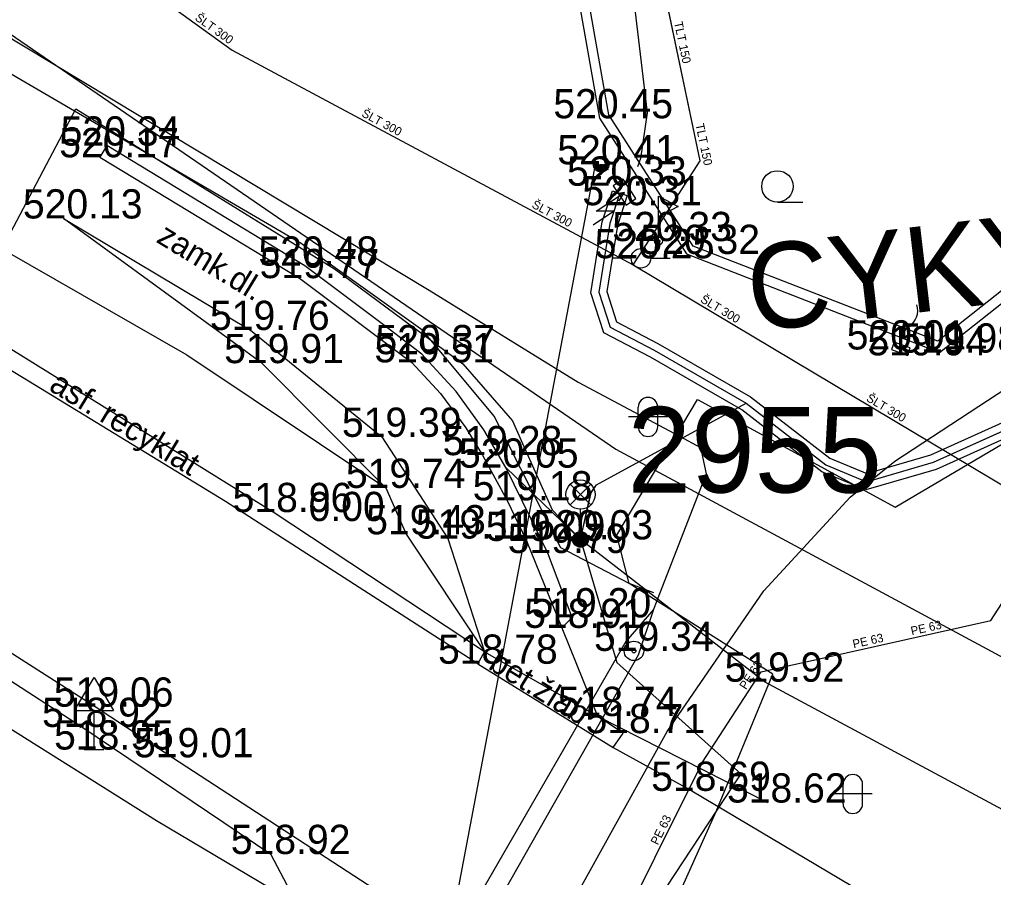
# Model space of a CAD drawing. Extents: x -668867 to -667827, y -1131943 to -1131019.
# Drawn here: x -668478.76 to -668453.79, y -1131449.79 to -1131427.79 of the extents above; entities that cross this region are included whole.
import ezdxf

# ---------------------------------------------------------------- set-up
doc = ezdxf.new("R2010")
doc.units = 0
for name, color, linetype in [('G_Bod_tecka', 7, 'Continuous'), ('G_Bod_vyska', 7, 'Continuous'), ('G_Breh_Teren', 7, 'Continuous'), ('G_Cesty_Schody', 7, 'Continuous'), ('G_Objekty_dopravni', 7, 'Continuous'), ('G_Objekty_technicke', 7, 'Continuous'), ('G_Plochy_zpevnene', 7, 'Continuous'), ('G_Ploty', 7, 'Continuous'), ('G_Popisy_povrchu', 7, 'Continuous'), ('G_Site-Rozvadece', 7, 'Continuous'), ('G_Site-Sloupy', 7, 'Continuous'), ('G_Site-vodovod', 7, 'Continuous'), ('G_Z_CHRANICKA-TEPLOVOD_kotovane', 7, 'Continuous'), ('G_Z_ELsilove_nadz_kotovane', 7, 'Continuous'), ('G_Z_ELsilove_podz_kotovane', 7, 'Continuous'), ('G_Z_PLYNY_podz_geodeticky', 7, 'Continuous'), ('G_Z_SPOJE_podz_geodeticky', 7, 'Continuous'), ('G_Z_SPOJE_podz_kotovane', 7, 'Continuous'), ('G_Z_SPOJE_podz_priblizne', 7, 'Continuous'), ('G_Z_VODA_podz_kotovane', 7, 'Continuous'), ('G_Zabradli_Svodidla', 7, 'Continuous'), ('G_Zelen-Znacky', 7, 'Continuous'), ('Vrstva 1', 7, 'Continuous'), ('Vrstva 17', 7, 'Continuous'), ('Vrstva 26', 7, 'Continuous'), ('Vrstva 3', 7, 'Continuous'), ('Vrstva 4', 7, 'Continuous'), ('Vrstva 6', 7, 'Continuous')]:
    doc.layers.add(name, color=color, linetype=linetype)

msp = doc.modelspace()

# ---------------------------------------------------------------- linework, layer by layer
at = {"layer": 'G_Bod_tecka'}
for p, q in [((-668463.89, -1131430.32), (-668463.89, -1131430.32)), ((-668476.52, -1131431.02), (-668476.52, -1131431.02)), ((-668476.7, -1131431.32), (-668476.7, -1131431.32)), ((-668463.85, -1131431.5), (-668463.85, -1131431.5)), ((-668463.54, -1131432.05), (-668463.54, -1131432.05)), ((-668463.21, -1131432.55), (-668463.21, -1131432.55)), ((-668477.63, -1131432.89), (-668477.63, -1131432.89)), ((-668462.38, -1131433.47), (-668462.38, -1131433.47)), ((-668462.83, -1131433.91), (-668462.83, -1131433.91)), ((-668461.66, -1131433.8), (-668461.66, -1131433.8)), ((-668471.45, -1131434.1), (-668471.45, -1131434.1)), ((-668471.58, -1131434.42), (-668471.58, -1131434.42)), ((-668472.84, -1131435.75), (-668472.84, -1131435.75)), ((-668468.45, -1131436.37), (-668468.45, -1131436.37)), ((-668456.41, -1131436.25), (-668456.41, -1131436.25)), ((-668456, -1131436.4), (-668456, -1131436.4)), ((-668455.18, -1131436.33), (-668455.18, -1131436.33)), ((-668472.55, -1131436.6), (-668472.55, -1131436.6)), ((-668468.7, -1131436.58), (-668468.7, -1131436.58)), ((-668469.47, -1131438.49), (-668469.47, -1131438.49)), ((-668466.89, -1131438.96), (-668466.89, -1131438.96)), ((-668466.29, -1131439.28), (-668466.29, -1131439.28)), ((-668469.37, -1131439.8), (-668469.37, -1131439.8)), ((-668466.26, -1131440.12), (-668466.26, -1131440.12)), ((-668472.26, -1131440.42), (-668472.26, -1131440.42)), ((-668470.57, -1131440.65), (-668470.57, -1131440.65)), ((-668468.85, -1131440.99), (-668468.85, -1131440.99)), ((-668467.78, -1131441.1), (-668467.78, -1131441.1)), ((-668465.76, -1131441.16), (-668465.76, -1131441.16)), ((-668464.38, -1131441.12), (-668464.38, -1131441.12)), ((-668465.22, -1131441.47), (-668465.22, -1131441.47)), ((-668464.59, -1131443.12), (-668464.59, -1131443.12)), ((-668464.86, -1131443.39), (-668464.86, -1131443.39)), ((-668463.01, -1131443.98), (-668463.01, -1131443.98)), ((-668467.01, -1131444.31), (-668467.01, -1131444.31)), ((-668459.66, -1131444.77), (-668459.66, -1131444.77)), ((-668476.82, -1131445.41), (-668476.82, -1131445.41)), ((-668463.94, -1131445.65), (-668463.94, -1131445.65)), ((-668477.16, -1131445.93), (-668477.16, -1131445.93)), ((-668463.29, -1131446.09), (-668463.29, -1131446.09)), ((-668476.85, -1131446.51), (-668476.85, -1131446.51)), ((-668474.84, -1131446.71), (-668474.84, -1131446.71)), ((-668461.53, -1131447.57), (-668461.53, -1131447.57)), ((-668459.59, -1131447.87), (-668459.59, -1131447.87)), ((-668472.32, -1131449.19), (-668472.32, -1131449.19))]:
    msp.add_line(p, q, dxfattribs=at)
at = {"layer": 'G_Breh_Teren'}
for p, q in [((-668464.38, -1131441.12), (-668466.29, -1131439.28)), ((-668459.66, -1131444.77), (-668464.38, -1131441.12)), ((-668463.94, -1131445.65), (-668459.59, -1131447.87))]:
    msp.add_line(p, q, dxfattribs=at)
for points in [[(-668469.37, -1131439.8), (-668472.55, -1131436.6), (-668477.63, -1131432.89)], [(-668479.2, -1131433.68), (-668474.47, -1131436.39), (-668469.37, -1131439.8), (-668468.85, -1131440.99), (-668466.84, -1131444)], [(-668466.84, -1131444), (-668472.26, -1131440.42), (-668481, -1131434.99)], [(-668410.2, -1131469.94), (-668412.45, -1131469.01), (-668422.03, -1131465.1), (-668426.97, -1131463.16), (-668431.89, -1131461.2), (-668435.72, -1131459.4), (-668438.96, -1131457.61), (-668444.44, -1131454.13), (-668452.52, -1131448.61), (-668459.66, -1131444.77)], [(-668464.92, -1131460.24), (-668470.3, -1131453.02), (-668472.32, -1131449.19)]]:
    msp.add_lwpolyline(points, dxfattribs=at)
at = {"layer": 'G_Cesty_Schody'}
msp.add_line((-668466.84, -1131444), (-668463.94, -1131445.65), dxfattribs=at)
at = {"layer": 'G_Objekty_dopravni'}
for p, q in [((-668477.35, -1131445.51), (-668476.85, -1131444.66)), ((-668476.85, -1131444.66), (-668476.35, -1131445.51)), ((-668477.35, -1131445.51), (-668476.35, -1131445.51)), ((-668476.85, -1131446.51), (-668476.85, -1131445.51)), ((-668477.1, -1131446.51), (-668476.6, -1131446.51))]:
    msp.add_line(p, q, dxfattribs=at)
at = {"layer": 'G_Objekty_technicke'}
for p, q in [((-668464.645, -1131439.705), (-668464.115, -1131440.235)), ((-668464.645, -1131440.235), (-668464.115, -1131439.705)), ((-668464.38, -1131441.12), (-668464.38, -1131440.345))]:
    msp.add_line(p, q, dxfattribs=at)
for centre, radius in [((-668464.38, -1131439.97), 0.375), ((-668464.38, -1131441.12), 0.2), ((-668464.38, -1131441.12), 0.18), ((-668464.38, -1131441.12), 0.16), ((-668464.38, -1131441.12), 0.14), ((-668464.38, -1131441.12), 0.12), ((-668464.38, -1131441.12), 0.1), ((-668464.38, -1131441.12), 0.08), ((-668464.38, -1131441.12), 0.06), ((-668464.38, -1131441.12), 0.04), ((-668464.38, -1131441.12), 0.02)]:
    msp.add_circle(centre, radius, dxfattribs=at)
at = {"layer": 'G_Plochy_zpevnene'}
for p, q in [((-668476.52, -1131431.02), (-668476.7, -1131431.32)), ((-668464.86, -1131443.39), (-668464.59, -1131443.12)), ((-668464.86, -1131443.39), (-668463.94, -1131445.65)), ((-668467.01, -1131444.31), (-668466.84, -1131444)), ((-668467.01, -1131444.31), (-668463.54, -1131446.46)), ((-668463.54, -1131446.46), (-668461.53, -1131447.57))]:
    msp.add_line(p, q, dxfattribs=at)
for points in [[(-668467.01, -1131444.31), (-668473.48, -1131440.15), (-668479.5, -1131436.47), (-668488.51, -1131430.88), (-668492.82, -1131428.04), (-668497.12, -1131424.95), (-668504.86, -1131419.02), (-668510.28, -1131414.86)], [(-668464.59, -1131443.12), (-668465.22, -1131441.47), (-668466.29, -1131439.28), (-668466.86, -1131438.31), (-668467.57, -1131437.33), (-668467.98, -1131436.88), (-668468.45, -1131436.37), (-668469.43, -1131435.62), (-668471.45, -1131434.1), (-668476.52, -1131431.02)], [(-668476.7, -1131431.32), (-668471.58, -1131434.42), (-668468.7, -1131436.58), (-668467.97, -1131437.38), (-668467.32, -1131438.26), (-668466.89, -1131438.96), (-668466.26, -1131440.12), (-668465.76, -1131441.16), (-668464.86, -1131443.39)], [(-668477.63, -1131432.89), (-668472.84, -1131435.75), (-668469.47, -1131438.49)], [(-668469.47, -1131438.49), (-668467.78, -1131441.1), (-668466.84, -1131444)], [(-668484.51, -1131440.49), (-668476.82, -1131445.41), (-668474.84, -1131446.71)], [(-668463.54, -1131446.46), (-668463.29, -1131446.09), (-668463.94, -1131445.65)], [(-668474.84, -1131446.71), (-668468.94, -1131450.55), (-668467.41, -1131451.55)], [(-668461.53, -1131447.57), (-668448.14, -1131455.53)]]:
    msp.add_lwpolyline(points, dxfattribs=at)
at = {"layer": 'G_Ploty'}
for p, q in [((-668422.71, -1131410.22), (-668455.22, -1131436.04)), ((-668455.18, -1131436.33), (-668422.58, -1131410.44)), ((-668465.97, -1131418.51), (-668463.89, -1131430.32)), ((-668463.65, -1131430.23), (-668465.7, -1131418.63)), ((-668463.89, -1131430.32), (-668461.66, -1131433.8)), ((-668461.49, -1131433.6), (-668463.65, -1131430.23)), ((-668455.22, -1131436.04), (-668461.49, -1131433.6)), ((-668461.66, -1131433.8), (-668455.18, -1131436.33))]:
    msp.add_line(p, q, dxfattribs=at)
at = {"layer": 'G_Site-Rozvadece'}
for p, q in [((-668463.98, -1131432.702), (-668463.25, -1131432.22)), ((-668463.25, -1131432.22), (-668463.515, -1131432.263)), ((-668463.394, -1131432.447), (-668463.25, -1131432.22)), ((-668464.052, -1131433.049), (-668463.53, -1131432.704)), ((-668463.53, -1131432.704), (-668463.98, -1131432.702))]:
    msp.add_line(p, q, dxfattribs=at)
for points in [[(-668463.29, -1131431.88), (-668463.54, -1131432.05), (-668463.21, -1131432.55), (-668462.96, -1131432.38)], [(-668456.34, -1131436.06), (-668456.41, -1131436.25), (-668456, -1131436.4), (-668455.93, -1131436.21)]]:
    msp.add_lwpolyline(points, close=True, dxfattribs=at)
for centre, start, end in [((-668456.236, -1131435.248), 303.0349, 16.7747), ((-668455.691, -1131436.086), 123.0349, 196.7747)]:
    msp.add_arc(centre, 0.5, start, end, dxfattribs=at)
at = {"layer": 'G_Site-Sloupy'}
for centre, radius in [((-668463.85, -1131431.5), 0.2), ((-668463.01, -1131443.98), 0.25), ((-668463.01, -1131443.98), 0.05)]:
    msp.add_circle(centre, radius, dxfattribs=at)
for radius in [0.18, 0.16, 0.14, 0.12, 0.1, 0.08, 0.06, 0.04, 0.02]:
    msp.add_arc((-668463.85, -1131431.5), radius, 180, 0, dxfattribs=at)
at = {"layer": 'G_Site-vodovod'}
for p, q in [((-668462.38, -1131433.47), (-668462.38, -1131432.32)), ((-668462.38, -1131432.32), (-668461.88, -1131432.585)), ((-668461.88, -1131432.585), (-668462.38, -1131432.85)), ((-668463.08, -1131433.91), (-668463.58, -1131433.91)), ((-668462.58, -1131433.91), (-668462.08, -1131433.91))]:
    msp.add_line(p, q, dxfattribs=at)
for centre, radius in [((-668462.38, -1131433.47), 0.1), ((-668462.38, -1131433.47), 0.0348), ((-668462.83, -1131433.91), 0.25)]:
    msp.add_circle(centre, radius, dxfattribs=at)
at = {"layer": 'G_Z_CHRANICKA-TEPLOVOD_kotovane'}
msp.add_lwpolyline([(-668451.154, -1131437.475), (-668455.261, -1131439.328), (-668457.062, -1131439.852), (-668458.191, -1131439.385), (-668460.242, -1131437.797), (-668462.586, -1131436.445), (-668463.785, -1131435.819), (-668464.115, -1131434.796), (-668463.825, -1131432.972), (-668463.56, -1131432.177), (-668463.18, -1131432.303), (-668463.435, -1131433.068), (-668463.705, -1131434.764), (-668463.455, -1131435.541), (-668462.394, -1131436.095), (-668460.018, -1131437.464), (-668457.989, -1131439.035), (-668457.038, -1131439.428), (-668455.399, -1131438.952), (-668451.306, -1131437.105)], dxfattribs=at)
at = {"layer": 'G_Z_ELsilove_nadz_kotovane'}
msp.add_lwpolyline([(-668464.007, -1131431.501), (-668468.689, -1131456.254)], dxfattribs=at)
at = {"layer": 'G_Z_ELsilove_podz_kotovane'}
for points in [[(-668462.466, -1131415.878), (-668463.066, -1131416.102), (-668465.12, -1131417.371), (-668464.957, -1131417.667), (-668464.671, -1131418.127), (-668463.236, -1131425.448), (-668462.671, -1131430.184), (-668462.843, -1131431.348), (-668462.921, -1131431.567)], [(-668479.08, -1131433.42), (-668477.32, -1131430.08), (-668470.69, -1131434.18), (-668467.4, -1131436.62), (-668466.12, -1131438.08), (-668465.9, -1131438.58), (-668465.11, -1131440.36), (-668464.38, -1131441.12), (-668464.11, -1131439.93), (-668463.97, -1131439.72), (-668460.13, -1131437.63), (-668458.09, -1131439.21), (-668457.05, -1131439.64), (-668455.33, -1131439.14), (-668451.23, -1131437.29), (-668445.76, -1131435.29), (-668442.87, -1131434.29), (-668441.69, -1131434.19), (-668441, -1131434.65), (-668440.33, -1131435.54)], [(-668464.007, -1131431.501), (-668463.674, -1131431.631)], [(-668463.37, -1131432.24), (-668463.63, -1131433.02), (-668463.91, -1131434.78), (-668463.62, -1131435.68), (-668462.49, -1131436.27), (-668460.13, -1131437.63), (-668458.09, -1131439.21), (-668457.05, -1131439.64), (-668455.33, -1131439.14), (-668451.23, -1131437.29), (-668445.76, -1131435.29), (-668444.08, -1131434.71), (-668442.87, -1131434.29), (-668441.69, -1131434.19), (-668441, -1131434.65)]]:
    msp.add_lwpolyline(points, dxfattribs=at)
at = {"layer": 'G_Z_PLYNY_podz_geodeticky'}
for points in [[(-668527.07, -1131410.75), (-668526.96, -1131410.87), (-668518.02, -1131418.51), (-668504.27, -1131428.9), (-668488.88, -1131439.82), (-668483.02, -1131443.45), (-668475.25, -1131448.33), (-668467.04, -1131453.21), (-668466.91, -1131453.3)], [(-668466.91, -1131453.3), (-668466.34, -1131453.63), (-668466.19, -1131453.33), (-668462.16, -1131446.05), (-668459.68, -1131442.44), (-668457.47, -1131440.04), (-668456.32, -1131439.11), (-668452.51, -1131436.62), (-668449.67, -1131435.17), (-668443.14, -1131432.27), (-668440.01, -1131430.74), (-668439.87, -1131430.65), (-668438.84, -1131430.02), (-668437.4, -1131432.29), (-668432.91, -1131437.47), (-668430.75, -1131440.01), (-668430.54, -1131440.3), (-668423.58, -1131448.32), (-668421.78, -1131450.38), (-668421.22, -1131451.02), (-668410.5, -1131463.68), (-668402.92, -1131461.91)]]:
    msp.add_lwpolyline(points, dxfattribs=at)
at = {"layer": 'G_Z_SPOJE_podz_geodeticky'}
for points in [[(-668583.62, -1131321.19), (-668582.19, -1131323.51), (-668579.37, -1131327.17), (-668571.26, -1131336.86), (-668560.31, -1131349.9), (-668548.78, -1131363.59), (-668541.66, -1131371.99), (-668528.88, -1131387.3), (-668520.15, -1131397.77), (-668514.25, -1131404.37), (-668511.63, -1131405.99), (-668507.04, -1131408.92), (-668502.16, -1131412.29), (-668495.34, -1131417.18), (-668487.38, -1131422.8), (-668480.13, -1131427.58), (-668468.26, -1131434.73), (-668464.44, -1131437.09), (-668461.84, -1131438.47)], [(-668504.73, -1131410.5), (-668463.47, -1131438.81), (-668419.51, -1131462.48), (-668373.54, -1131482.21), (-668331.41, -1131509.31)], [(-668461.84, -1131438.47), (-668461.3, -1131438.76)], [(-668461.3, -1131438.76), (-668461.16, -1131439.44), (-668462.46, -1131442.78)], [(-668462.51, -1131442.92), (-668463.22, -1131443.74), (-668467.94, -1131451.93), (-668467.94, -1131452.6), (-668467.69, -1131453.33)], [(-668462.51, -1131442.92), (-668462.9, -1131444.09), (-668467.46, -1131452.12), (-668467.64, -1131452.72), (-668467.69, -1131453.33)], [(-668462.46, -1131442.78), (-668462.51, -1131442.92)]]:
    msp.add_lwpolyline(points, dxfattribs=at)
at = {"layer": 'G_Z_SPOJE_podz_kotovane'}
for points in [[(-668463.13, -1131442.25), (-668464.88, -1131441.34), (-668466.59, -1131437.96), (-668468.42, -1131435.76), (-668471.54, -1131433.53), (-668482.25, -1131427.27), (-668487.56, -1131424.24), (-668492.8, -1131420.67), (-668510.89, -1131407.04), (-668515.03, -1131403.42), (-668521.28, -1131395.98)], [(-668463.13, -1131442.25), (-668463.45, -1131441.01), (-668461.38, -1131437.53), (-668456.31, -1131440.29), (-668445.54, -1131433.93), (-668442.84, -1131433.81), (-668440.64, -1131435.22)], [(-668464.48, -1131457.55), (-668463.72, -1131454.38), (-668460.9, -1131448.1), (-668459.45, -1131444.58), (-668463.13, -1131442.25)], [(-668462.5, -1131442.49), (-668463.13, -1131442.25)]]:
    msp.add_lwpolyline(points, dxfattribs=at)
at = {"layer": 'G_Z_SPOJE_podz_priblizne'}
msp.add_lwpolyline([(-668504.73, -1131410.5), (-668463.47, -1131438.81), (-668419.51, -1131462.48), (-668373.54, -1131482.21), (-668331.41, -1131509.31)], dxfattribs=at)
at = {"layer": 'G_Z_VODA_podz_kotovane'}
for points in [[(-668683.369, -1131181.224), (-668649.8, -1131211.72), (-668646.34, -1131215.79), (-668601.09, -1131269.33), (-668550.43, -1131331.42), (-668550.07, -1131333.92), (-668545.5, -1131360.28), (-668544.8, -1131361.58), (-668534.06, -1131374.68), (-668512.85, -1131400.04), (-668473.31, -1131428.57), (-668463.03, -1131434.08), (-668452.78, -1131440.2), (-668452.76, -1131440.21)], [(-668463.03, -1131434.08), (-668462.87, -1131433.83), (-668461.31, -1131431.41), (-668465.17, -1131413.01)], [(-668434.73, -1131472.73), (-668436.68, -1131471.68), (-668438.61, -1131470.64), (-668443.89, -1131467.82), (-668450.26, -1131464.4), (-668451.23, -1131463.88), (-668455.97, -1131461.29), (-668459.35, -1131459.44), (-668460.93, -1131458.58), (-668462.93, -1131456.81), (-668464.59, -1131455.47), (-668464.93, -1131454.21), (-668461.25, -1131446.83), (-668459.75, -1131444.52), (-668453.86, -1131443.2), (-668452.53, -1131441.14), (-668452.41, -1131441.01)]]:
    msp.add_lwpolyline(points, dxfattribs=at)
at = {"layer": 'G_Zabradli_Svodidla'}
for p, q in [((-668484.9, -1131440.92), (-668477.16, -1131445.93)), ((-668477.16, -1131445.93), (-668472.32, -1131449.19))]:
    msp.add_line(p, q, dxfattribs=at)
at = {"layer": 'G_Zelen-Znacky'}
for p, q in [((-668459.332, -1131432.47), (-668458.682, -1131432.467)), ((-668462.9, -1131438.23), (-668462.9, -1131437.73)), ((-668462.4, -1131438.23), (-668462.4, -1131437.73)), ((-668462.15, -1131437.98), (-668463.15, -1131437.98)), ((-668457.65, -1131447.9), (-668457.65, -1131447.4)), ((-668457.15, -1131447.9), (-668457.15, -1131447.4)), ((-668456.9, -1131447.65), (-668457.9, -1131447.65))]:
    msp.add_line(p, q, dxfattribs=at)
msp.add_circle((-668459.332, -1131432.067), 0.403, dxfattribs=at)
for centre, start, end in [((-668462.65, -1131437.73), 0, 180), ((-668462.65, -1131438.23), 180, 0), ((-668457.4, -1131447.4), 0, 180), ((-668457.4, -1131447.9), 180, 0)]:
    msp.add_arc(centre, 0.25, start, end, dxfattribs=at)
at = {"layer": 'Vrstva 1'}
for p, q in [((-668455.33, -1131439.14), (-668451.23, -1131437.29)), ((-668463.97, -1131439.72), (-668460.13, -1131437.63)), ((-668460.13, -1131437.63), (-668458.09, -1131439.21)), ((-668457.05, -1131439.64), (-668455.33, -1131439.14)), ((-668458.09, -1131439.21), (-668457.05, -1131439.64)), ((-668464.38, -1131441.12), (-668464.112, -1131439.926)), ((-668464.112, -1131439.926), (-668463.97, -1131439.72)), ((-668464.38, -1131441.12), (-668464.38, -1131441.12)), ((-668464.38, -1131441.12), (-668463.451, -1131444.28)), ((-668463.451, -1131444.28), (-668460.27, -1131447.137)), ((-668460.27, -1131447.137), (-668460.456, -1131447.419)), ((-668460.456, -1131447.419), (-668464.93, -1131454.21))]:
    msp.add_line(p, q, dxfattribs=at)
at = {"layer": 'Vrstva 17'}
for p, q in [((-668479.08, -1131433.42), (-668477.32, -1131430.08)), ((-668477.32, -1131430.08), (-668470.69, -1131434.18)), ((-668470.69, -1131434.18), (-668467.4, -1131436.62)), ((-668467.4, -1131436.62), (-668466.12, -1131438.08)), ((-668466.12, -1131438.08), (-668465.9, -1131438.58)), ((-668465.9, -1131438.58), (-668465.11, -1131440.36)), ((-668465.11, -1131440.36), (-668464.38, -1131441.12))]:
    msp.add_line(p, q, dxfattribs=at)
at = {"layer": 'Vrstva 26'}
for points in [[(-668683.369, -1131181.224), (-668649.798, -1131211.717), (-668646.336, -1131215.786), (-668601.09, -1131269.326), (-668550.43, -1131331.42), (-668550.07, -1131333.92), (-668545.496, -1131360.279), (-668544.8, -1131361.58), (-668534.06, -1131374.68), (-668512.85, -1131400.04), (-668473.31, -1131428.57), (-668463.033, -1131434.082), (-668452.779, -1131440.199), (-668452.76, -1131440.21)], [(-668463.033, -1131434.082), (-668462.87, -1131433.83), (-668461.31, -1131431.41), (-668465.171, -1131413.013)], [(-668434.733, -1131472.726), (-668436.677, -1131471.683), (-668438.615, -1131470.642), (-668443.886, -1131467.815), (-668450.263, -1131464.398), (-668451.23, -1131463.88), (-668455.966, -1131461.292), (-668459.354, -1131459.441), (-668460.93, -1131458.58), (-668462.929, -1131456.807), (-668464.59, -1131455.47), (-668464.93, -1131454.21), (-668461.25, -1131446.83), (-668459.75, -1131444.52), (-668453.86, -1131443.2), (-668452.53, -1131441.14), (-668452.41, -1131441.01)]]:
    msp.add_lwpolyline(points, dxfattribs=at)
at = {"layer": 'Vrstva 6'}
msp.add_line((-668462.87, -1131433.83), (-668462.87, -1131433.83), dxfattribs=at)

# ---------------------------------------------------------------- texts
at = {"layer": 'G_Bod_vyska'}
for s, p in [('520.45', (-668465.076, -1131430.32)), ('520.34', (-668477.706, -1131431.02)), ('520.17', (-668477.744, -1131431.32)), ('520.41', (-668464.974, -1131431.5)), ('520.33', (-668464.726, -1131432.05)), ('520.31', (-668464.334, -1131432.55)), ('520.13', (-668478.674, -1131432.89)), ('520.33', (-668463.566, -1131433.47)), ('520.25', (-668464.016, -1131433.91)), ('520.32', (-668462.846, -1131433.8)), ('520.48', (-668472.636, -1131434.1)), ('519.77', (-668472.604, -1131434.42)), ('519.76', (-668473.878, -1131435.75)), ('520.37', (-668469.636, -1131436.37)), ('520.01', (-668457.556, -1131436.25)), ('519.94', (-668457.026, -1131436.4)), ('519.98', (-668456.206, -1131436.33)), ('519.91', (-668473.514, -1131436.6)), ('519.51', (-668469.663, -1131436.58)), ('519.39', (-668470.496, -1131438.49)), ('519.28', (-668467.914, -1131438.96)), ('520.05', (-668467.497, -1131439.28)), ('519.74', (-668470.394, -1131439.8)), ('519.18', (-668467.143, -1131440.12)), ('518.96', (-668473.298, -1131440.42)), ('0.00', (-668471.35, -1131440.65)), ('519.43', (-668469.874, -1131440.99)), ('519.11', (-668468.601, -1131441.1)), ('519.09', (-668466.808, -1131441.16)), ('520.03', (-668465.587, -1131441.12)), ('519.79', (-668466.246, -1131441.47)), ('519.20', (-668465.636, -1131443.12)), ('518.91', (-668465.823, -1131443.39)), ('519.34', (-668464.034, -1131443.98)), ('518.78', (-668468.032, -1131444.31)), ('519.92', (-668460.686, -1131444.77)), ('519.06', (-668477.88, -1131445.41)), ('518.74', (-668464.962, -1131445.65)), ('518.92', (-668478.184, -1131445.93)), ('518.71', (-668464.251, -1131446.09)), ('518.95', (-668477.874, -1131446.51)), ('519.01', (-668475.824, -1131446.71)), ('518.69', (-668462.568, -1131447.57)), ('518.62', (-668460.626, -1131447.87)), ('518.92', (-668473.344, -1131449.19))]:
    msp.add_text(s, height=0.75, dxfattribs=at).set_placement(p)
at = {"layer": 'G_Popisy_povrchu'}
for s, rotation, p in [('zamk.dl.', 328.7602, (-668475.283, -1131433.48)), ('asf. recyklat', 328.6206, (-668478.036, -1131437.277)), ('bet.žlab', 328.2178, (-668466.774, -1131444.421))]:
    msp.add_text(s, height=0.6, rotation=rotation, dxfattribs=at).set_placement(p)
at = {"layer": 'Vrstva 3'}
msp.add_text('CYKY 5Cx10', height=2.1939, rotation=6.6925, dxfattribs=at).set_placement((-668459.975, -1131435.803))
at = {"layer": 'Vrstva 4'}
for s, rotation, p in [('ŠLT 300', 324.1907, (-668474.28, -1131427.783)), ('TLT 150', 281.8403, (-668461.983, -1131427.861)), ('ŠLT 300', 331.7537, (-668470.011, -1131430.259)), ('TLT 150', 281.8711, (-668461.434, -1131430.476)), ('ŠLT 300', 331.7537, (-668465.647, -1131432.599)), ('ŠLT 300', 329.1568, (-668461.325, -1131435.019)), ('ŠLT 300', 329.2109, (-668457.072, -1131437.556)), ('PE 63', 12.6482, (-668455.887, -1131443.582)), ('PE 63', 12.6394, (-668457.377, -1131443.916)), ('PE 63', 57.0197, (-668460.139, -1131444.99)), ('PE 63', 63.4976, (-668462.398, -1131448.975))]:
    msp.add_text(s, height=0.2194, rotation=rotation, dxfattribs=at).set_placement(p)
msp.add_text('2955', height=2.1939, dxfattribs=at).set_placement((-668463.177, -1131439.918))

doc.saveas('drawing.dxf')
